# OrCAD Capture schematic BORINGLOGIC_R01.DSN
size A3; title: Boring Logic; rev: R01; note: USB Logic 8
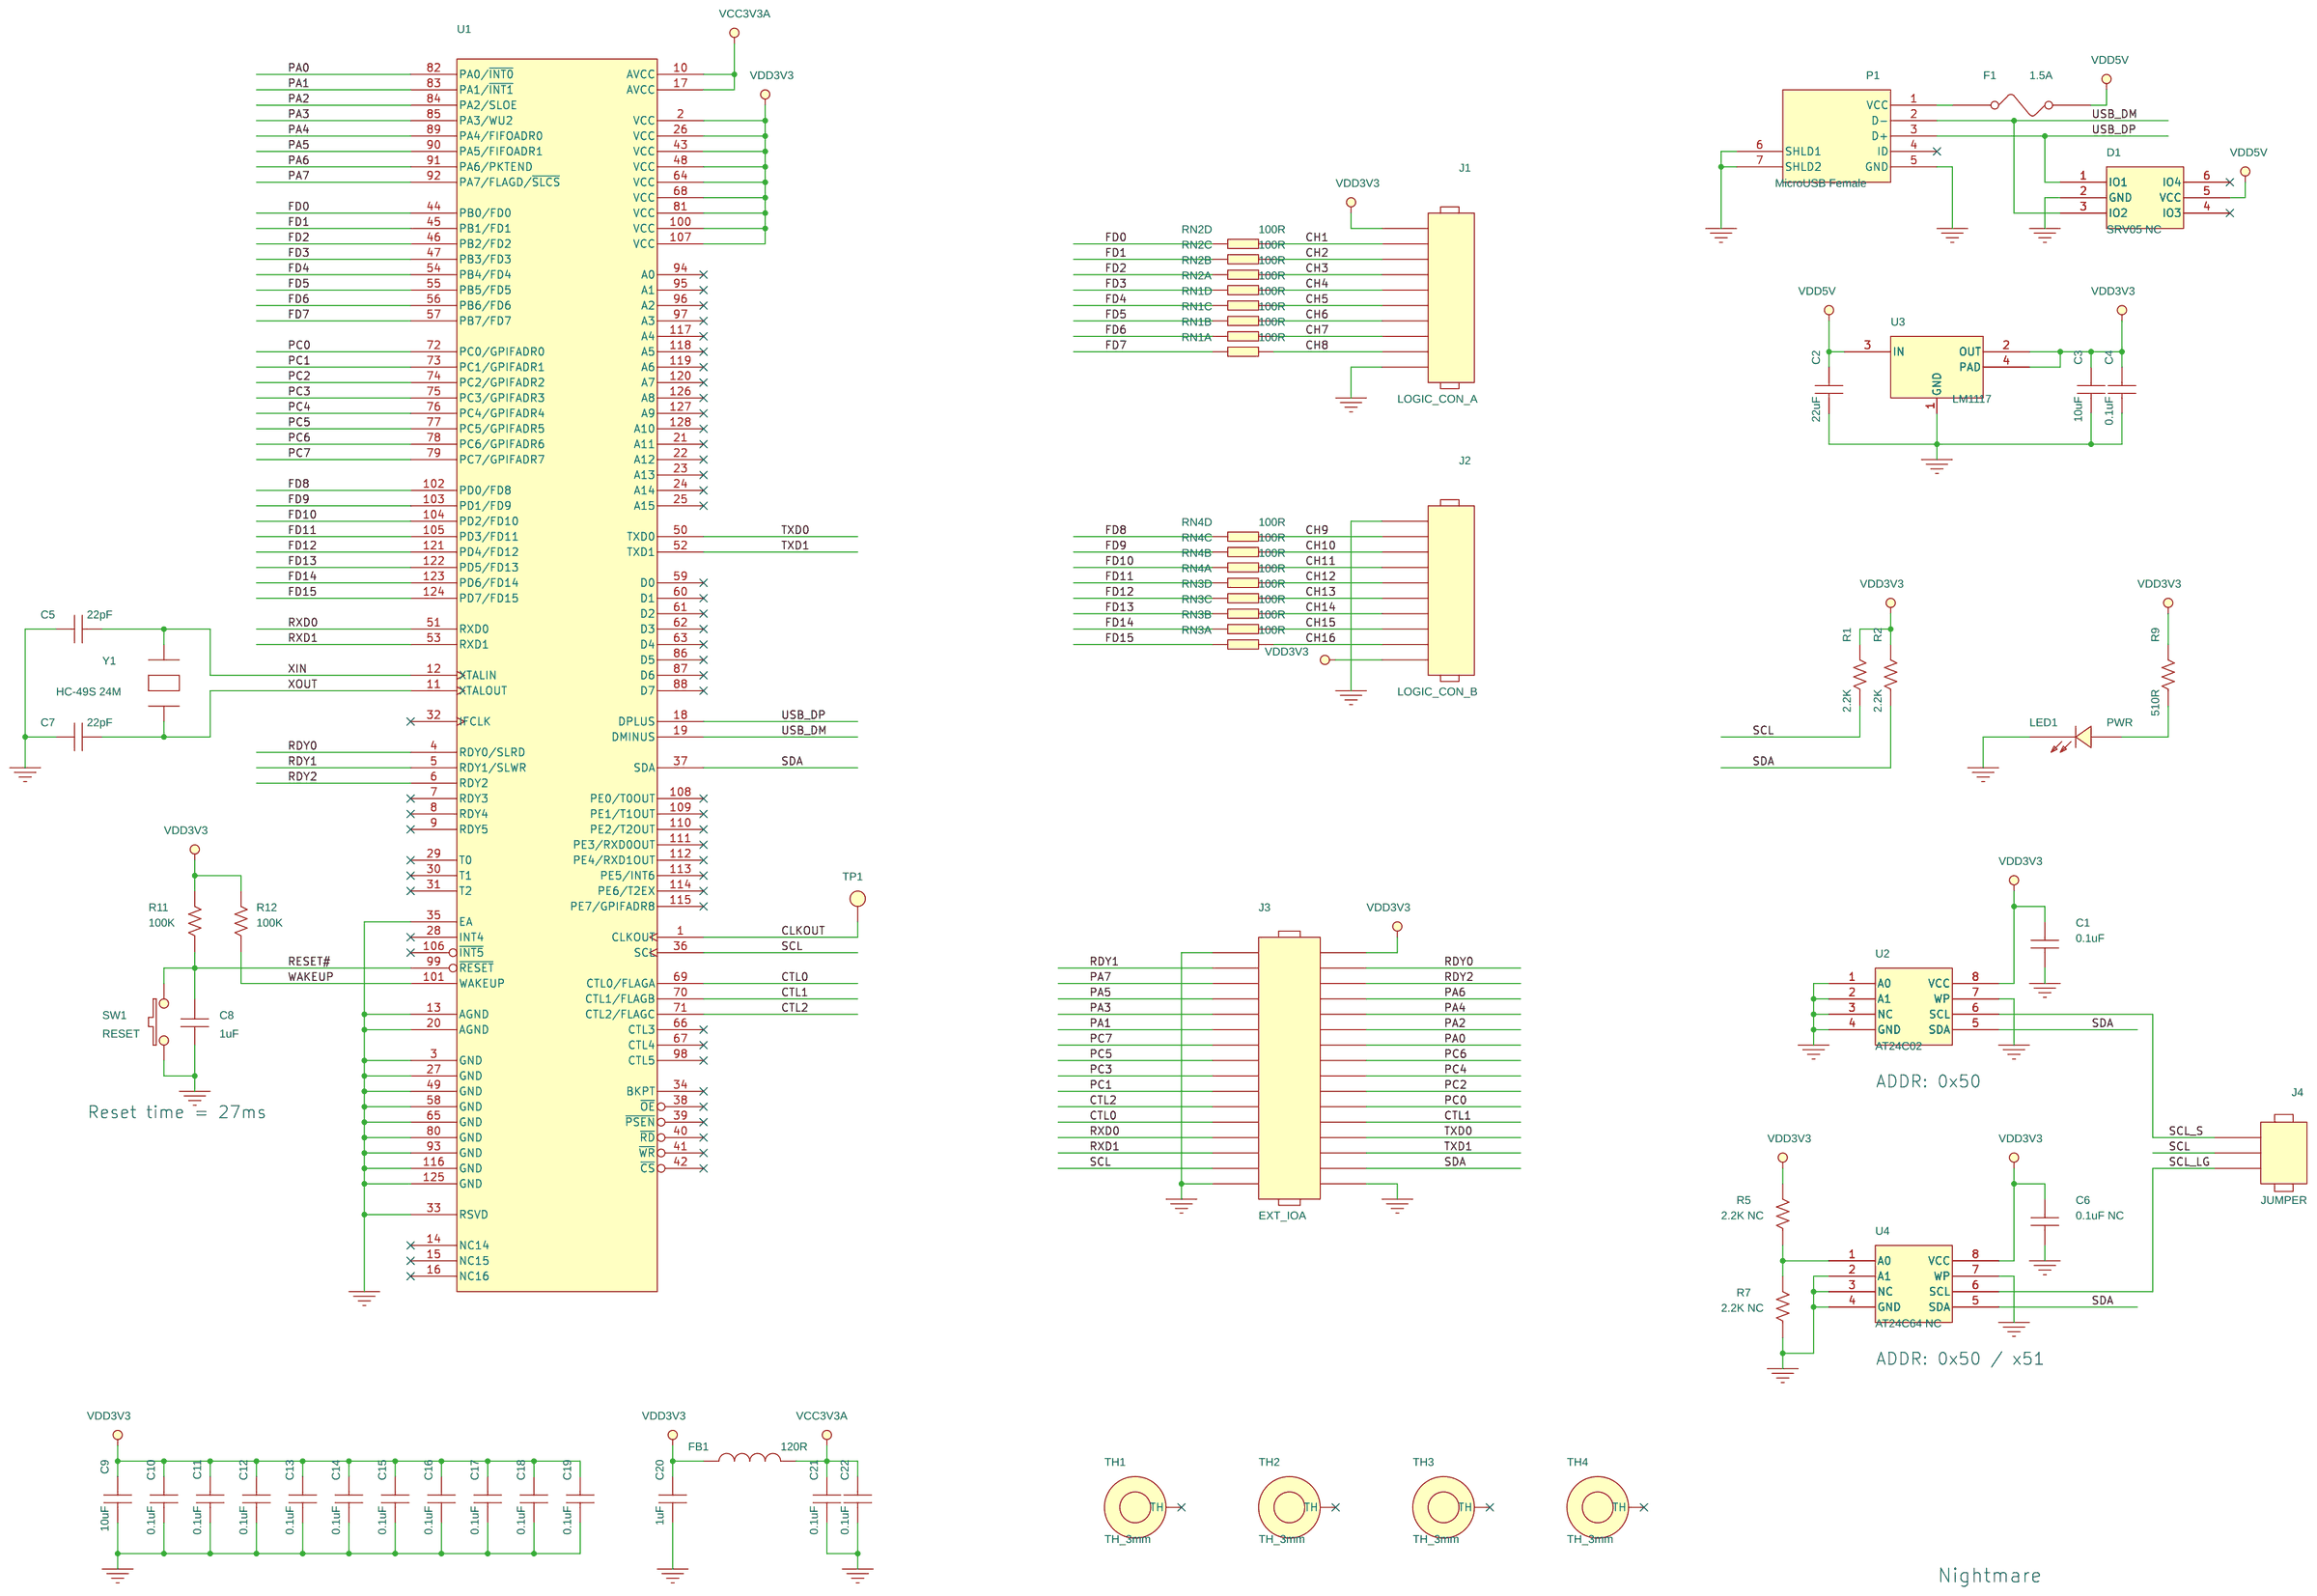
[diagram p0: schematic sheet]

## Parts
C1  0.1uF  [C0603]
C2  22uF  [C1206]
C3  10uF  [C0805]
C4  0.1uF  [C0603]
C5  22pF  [C0603]
C6  0.1uF NC  [C0603]
C7  22pF  [C0603]
C8  1uF  [C0603]
C9  10uF  [C0805]
C10  0.1uF  [C0603]
C11  0.1uF  [C0603]
C12  0.1uF  [C0603]
C13  0.1uF  [C0603]
C14  0.1uF  [C0603]
C15  0.1uF  [C0603]
C16  0.1uF  [C0603]
C17  0.1uF  [C0603]
C18  0.1uF  [C0603]
C19  0.1uF  [C0603]
C20  1uF  [C0603]
C21  0.1uF  [C0603]
C22  0.1uF  [C0603]
D1  SRV05 NC  [SOT23-6]
F1  1.5A  [R1206]
FB1  120R  [R0603]
J1  LOGIC_CON_A  [SIP10]
J2  LOGIC_CON_B  [SIP10]
J3  EXT_IOA  [SIP16X2_2mm]
J4  JUMPER  [SIP3]
LED1  PWR  [LED0805]
P1  MicroUSB Female  [USB_MICRO_F_SMT]
R1  2.2K  [R0603]
R2  2.2K  [R0603]
R5  2.2K NC  [R0603]
R7  2.2K NC  [R0603]
R9  510R  [R0603]
R11  100K  [R0603]
R12  100K  [R0603]
RN1  100R  [RN0603]  (sections A,B,C,D)
RN2  100R  [RN0603]  (sections A,B,C,D)
RN3  100R  [RN0603]  (sections A,B,C,D)
RN4  100R  [RN0603]  (sections A,B,C,D)
SW1  RESET  [SW_2P_SMT]
TH1  TH_3mm  [TH3_0]
TH2  TH_3mm  [TH3_0]
TH3  TH_3mm  [TH3_0]
TH4  TH_3mm  [TH3_0]
TP1  VO  [TP5030]
U1  CY7C68013A  [QFP128A]
U2  AT24C02  [SO8]
U3  LM1117  [SOT223]
U4  AT24C64 NC  [SO8]
Y1  HC-49S 24M  [HC-49S]

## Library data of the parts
C1 C4-C22 = CAP_NP
C2 C3 = CAP_CE_0603
D1 = SRV05-4
F1 = FUSE
FB1 = FB: PSpiceTemplate: L^@REFDES %1 %2 ?TOLERANCE|L^@REFDES| @VALUE ?IC/IC=@IC/ ?TOLERANCE|\n.model l^@REFDES IND L=1 DEV=@TOLERANCE% TC1=@TC1 TC2=@T
J1 J2 = HEADER_10
J3 = HEADER_16X2
J4 = HEADER_3
LED1 = LED_0805
P1 = CON_USB_MICRO_F
R1 R2 R5 R7 R9 R11 R12 = R: PSpiceTemplate: R^@REFDES %1 %2 ?TOLERANCE|R^@REFDES| @VALUE TC=@TC1,@TC2 ?TOLERANCE|\n.model R^@REFDES RES R=1 DEV=@TOLERANCE% TC1=@TC1 TC2=@
RN1-RN4 = 8P4R_0402
SW1 = SW_PUSHBUTTON
TH1-TH4 = THROUGH_HOLE
TP1 = T_POINT_R
U1 = CY7C68013A_128P: ICA_MFR_NAME: CYPRESS SEMICONDUCTOR CORP; ICA_PARTNUM: $$2169747$$CY7C68013A-128AXC; Part Number: TMP-13
U2 U4 = AT24C512
U3 = LM1117
Y1 = HC-49S

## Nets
GND: C1.2 C2.2 C3.2 C4.2 C5.1 C6.2 C7.1 C8.1 C9.2 C10.2 C11.2 C12.2 C13.2 C14.2 C15.2 C16.2 C17.2 C18.2 C19.2 C20.2 C21.2 C22.2 D1.2(GND) J1.10 J2.10 J3.2 J3.31 J3.32 LED1.2(CATHODE) P1.5(GND) P1.6(SHLD1) P1.7(SHLD2) R7.1 SW1.1 U1.3(GND) U1.13(AGND) U1.20(AGND) U1.27(GND) U1.33(RSVD) U1.35(EA) U1.49(GND) U1.58(GND) U1.65(GND) U1.80(GND) U1.93(GND) U1.116(GND) U1.125(GND) U2.1(A0) U2.2(A1) U2.3(NC) U2.4(GND) U2.7(WP) U3.1(GND) U4.2(A1) U4.3(NC) U4.4(GND) U4.7(WP)
VCC3V3A: C21.1 C22.1 FB1.2 U1.10(AVCC) U1.17(AVCC)
VDD3V3: C1.1 C3.1 C4.1 C6.1 C9.1 C10.1 C11.1 C12.1 C13.1 C14.1 C15.1 C16.1 C17.1 C18.1 C19.1 C20.1 FB1.1 J1.1 J2.1 J3.1 R1.2 R2.2 R5.2 R9.2 R11.2 R12.2 U1.2(VCC) U1.26(VCC) U1.43(VCC) U1.48(VCC) U1.64(VCC) U1.68(VCC) U1.81(VCC) U1.100(VCC) U1.107(VCC) U2.8(VCC) U3.2(OUT) U3.4(PAD) U4.8(VCC)
VDD5V: C2.1 D1.5(VCC) F1.2 U3.3(IN)
CH1: J1.2 RN2.5
CH2: J1.3 RN2.6(5)
CH3: J1.4 RN2.7(5)
CH4: J1.5 RN2.8(5)
CH5: J1.6 RN1.5
CH6: J1.7 RN1.6(5)
CH7: J1.8 RN1.7(5)
CH8: J1.9 RN1.8(5)
CH9: J2.9 RN4.5
CH10: J2.8 RN4.6(5)
CH11: J2.7 RN4.7(5)
CH12: J2.6 RN4.8(5)
CH13: J2.5 RN3.5
CH14: J2.4 RN3.6(5)
CH15: J2.3 RN3.7(5)
CH16: J2.2 RN3.8(5)
CLKOUT: TP1.1(TP) U1.1(CLKOUT)
CTL0: J3.24 U1.69(CTL0/FLAGA)
CTL1: J3.23 U1.70(CTL1/FLAGB)
CTL2: J3.22 U1.71(CTL2/FLAGC)
FD0: RN2.4 U1.44(PB0/FD0)
FD1: RN2.3(4) U1.45(PB1/FD1)
FD2: RN2.2(4) U1.46(PB2/FD2)
FD3: RN2.1(4) U1.47(PB3/FD3)
FD4: RN1.4 U1.54(PB4/FD4)
FD5: RN1.3(4) U1.55(PB5/FD5)
FD6: RN1.2(4) U1.56(PB6/FD6)
FD7: RN1.1(4) U1.57(PB7/FD7)
FD8: RN4.4 U1.102(PD0/FD8)
FD9: RN4.3(4) U1.103(PD1/FD9)
FD10: RN4.2(4) U1.104(PD2/FD10)
FD11: RN4.1(4) U1.105(PD3/FD11)
FD12: RN3.4 U1.121(PD4/FD12)
FD13: RN3.3(4) U1.122(PD5/FD13)
FD14: RN3.2(4) U1.123(PD6/FD14)
FD15: RN3.1(4) U1.124(PD7/FD15)
PA0: J3.13 U1.82(PA0/~{INT0})
PA1: J3.12 U1.83(PA1/~{INT1})
PA2: J3.11 U1.84(PA2/SLOE)
PA3: J3.10 U1.85(PA3/WU2)
PA4: J3.9 U1.89(PA4/FIFOADR0)
PA5: J3.8 U1.90(PA5/FIFOADR1)
PA6: J3.7 U1.91(PA6/PKTEND)
PA7: J3.6 U1.92(PA7/FLAGD/~{SLCS})
PC0: J3.21 U1.72(PC0/GPIFADR0)
PC1: J3.20 U1.73(PC1/GPIFADR1)
PC2: J3.19 U1.74(PC2/GPIFADR2)
PC3: J3.18 U1.75(PC3/GPIFADR3)
PC4: J3.17 U1.76(PC4/GPIFADR4)
PC5: J3.16 U1.77(PC5/GPIFADR5)
PC6: J3.15 U1.78(PC6/GPIFADR6)
PC7: J3.14 U1.79(PC7/GPIFADR7)
RDY0: J3.3 U1.4(RDY0/SLRD)
RDY1: J3.4 U1.5(RDY1/SLWR)
RDY2: J3.5 U1.6(RDY2)
RESET#: C8.2 R11.1 SW1.2 U1.99(~{RESET})
RXD0: J3.26 U1.51(RXD0)
RXD1: J3.28 U1.53(RXD1)
SCL: J3.30 J4.2 R1.1 U1.36(SCL)
SCL_LG: J4.3 U4.6(SCL)
SCL_S: J4.1 U2.6(SCL)
SDA: J3.29 R2.1 U1.37(SDA) U2.5(SDA) U4.5(SDA)
TXD0: J3.25 U1.50(TXD0)
TXD1: J3.27 U1.52(TXD1)
USB_DM: D1.3(IO2) P1.2(D-) U1.19(DMINUS)
USB_DP: D1.1(IO1) P1.3(D+) U1.18(DPLUS)
WAKEUP: R12.1 U1.101(WAKEUP)
XIN: C5.2 U1.12(XTALIN) Y1.1
XOUT: C7.2 U1.11(XTALOUT) Y1.2
N1173626: F1.1 P1.1(VCC)
N1191686: R5.1 R7.2 U4.1(A0)
N1227883: LED1.1(ANODE) R9.1

Not connected (* = marked no-connect by the designer): D1 4(IO3)* 6(IO4)*; P1 4(ID)*; TH1 1(TH)*; TH2 1(TH)*; TH3 1(TH)*; TH4 1(TH)*; U1 7(RDY3)* 8(RDY4)* 9(RDY5)* 14(NC14)* 15(NC15)* 16(NC16)* 21(A11)* 22(A12)* 23(A13)* 24(A14)* 25(A15)* 28(INT4)* 29(T0)* 30(T1)* 31(T2)* 32(IFCLK)* 34(BKPT)* 38(~{OE})* 39(~{PSEN})* 40(~{RD})* 41(~{WR})* 42(~{CS})* 59(D0)* 60(D1)* 61(D2)* 62(D3)* 63(D4)* 66(CTL3)* 67(CTL4)* 86(D5)* 87(D6)* 88(D7)* 94(A0)* 95(A1)* 96(A2)* 97(A3)* 98(CTL5)* 106(~{INT5})* 108(PE0/T0OUT)* 109(PE1/T1OUT)* 110(PE2/T2OUT)* 111(PE3/RXD0OUT)* 112(PE4/RXD1OUT)* 113(PE5/INT6)* 114(PE6/T2EX)* 115(PE7/GPIFADR8)* 117(A4)* 118(A5)* 119(A6)* 120(A7)* 126(A8)* 127(A9)* 128(A10)*

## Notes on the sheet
- ADDR: 0x50
- Reset time = 27ms
- ADDR: 0x50 / x51
- Nightmare
